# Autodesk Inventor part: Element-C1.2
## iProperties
Created: 2007-03
Part Number: Element-C1.2
Project: Anlage
Cost Center: 0 kg
Material: Stahl (allgemein)
Description: Benennung
Document SubType Name: Blech
Designer: Cadkon/Ge
Authority: 0 mm^3
SaveDate: 2005-04-14
SaveTime: 20:51
TotalMass: 0 kg
TotalVolume: 0 mm^3
SM_Thickness: 1 mm
SM_Style: Default
SM_Extents: N/A
SM_Extents_Width: 0,00 mm
SM_Extents_Length: 0,00 mm
Author: Cadkon/Ge
Revision Number: Zeichnungsindex
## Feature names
1. Wandstärke1
2. Griffschale_L [Extrusion]
3. Griffschale_R [Extrusion]
4. BT1_S1_1 [Hole]
5. BT1_S1_2 [Hole]
6. BT1_S1_3 [Hole]
7. BT1_S1_4 [Hole]
8. BT1_S1_5 [Hole]
9. BT1_S1_6 [Hole]
10. BT1_S1_7 [Hole]
11. Grobblech7
